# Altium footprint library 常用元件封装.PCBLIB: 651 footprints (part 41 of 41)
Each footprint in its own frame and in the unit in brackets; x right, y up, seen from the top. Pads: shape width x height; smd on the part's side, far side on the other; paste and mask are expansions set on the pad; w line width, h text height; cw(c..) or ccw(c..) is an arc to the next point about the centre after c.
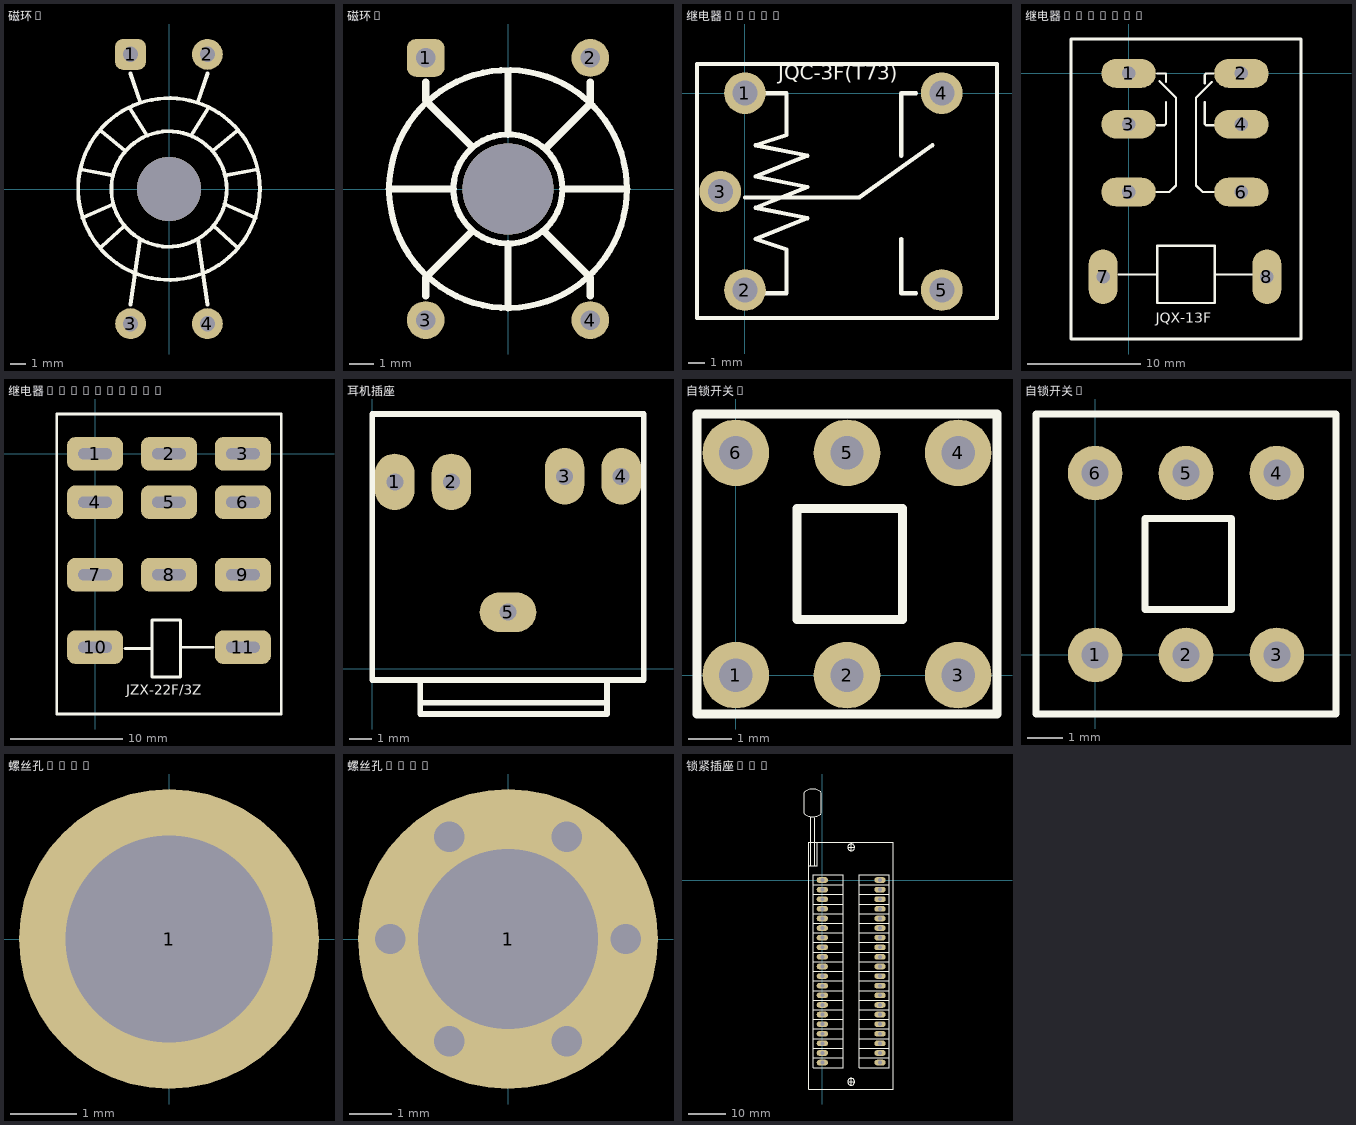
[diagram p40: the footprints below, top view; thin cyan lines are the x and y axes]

## 磁环1 [mil] "外径12mm脚距17.78mm"
pads (4):
  rrect50% 80x80 hole 40: 1(-100,350)
  round 80 hole 40: 2(100,350) 3(-100,-350) 4(100,-350)
via 0,0 diameter 165.35 hole 165.35
TopOverlay:
  circle w10: c0,0 r236.22
  circle w10: c0,0 r150
  lines w10: -225,-75 -145,-40 ; -225,50 -145,35 ; -175,-150 -117.72,-97.49 ; -175,150 -115,100 ; -102.75,211.4 -58.65,140.84 ; -100,-300 -75.7,-129.9 ; -100,300 -75,225 ; 57.25,138.6 102.75,211.4 ; 75,225 100,300 ; 75.7,-129.9 100,-300 ; 115,-95 175,-150 ; 115,100 175,150 ; 145,-40 225,-75 ; 145,35 225,50

## 磁环2 [mil] "外径11mm脚距12mm"
pads (4):
  rrect50% 62x62 hole 32: 1(-135,215)
  round 62 hole 32: 2(135,215) 3(-135,-215) 4(135,-215)
via 0,0 diameter 150 hole 150
TopOverlay:
  circle w10: c0,0 r89.44
  circle w10: c0,0 r195
  lines w12: -195,0 -90,0 ; -135,-175 -135,-155 -135,-145 -60,-70 ; -135,145 -135,175 ; -130,140 -60,70 ; 0,-195 0,-90 ; 0,90 0,190 ; 60,-70 135,-145 135,-175 ; 65,70 135,140 135,175 ; 89.44,0 195,0

## 继电器(T73) [mm] "长19mm宽15mm"
height 15
pads (5):
  round 2.54 hole 1.524: 1(0,0) 2(0,-12) 3(-1.5,-6) 4(12,0) 5(12,-12)
TopOverlay:
  lines w0.254: 0,-6.35 6.985,-6.35 11.43,-3.175 ; 1.27,-12.2 2.54,-12.2 2.54,-9.525 0.635,-8.89 3.81,-7.62 0.635,-6.985 3.81,-5.715 0.635,-5.08 3.81,-3.81 0.635,-3.175 2.54,-2.54 2.54,0 1.27,0 ; 9.525,-8.89 9.525,-12.2 10.43,-12.2 ; 9.525,-3.81 9.525,0 10.43,0 ; -2.921,-13.716 15.367,-13.716 15.367,1.778 -2.921,1.778 -2.921,-13.716
  text "JQC-3F(T73)" at 2.032,0.508 h1.52

## 继电器JQX-13F [mil] "长21mm宽11mm"
pads (8):
  oval 190x100 hole 47.24: 1(0,0) 2(393,0) 3(0,-177) 4(393,-177) 5(0,-413) 6(393,-413)
  oval 100x190 hole 47.24: 7(-89,-708) 8(482,-708)
TopOverlay:
  lines w7.87: -35,-700 100,-700 ; 0,-413 142,-413 165,-390 165,-85 107.5,-27.5 ; 100,-180 125,-180 130,-175 130,-100 ; 100,0 130,0 130,-30 ; 265,-100 265,-175 270,-180 300,-180 ; 265,-35 265,-5 270,0 295,0 ; 290,-30 235,-85 235,-390 258,-413 393,-413 ; 300,-700 435,-700 ; 100,-800 300,-800 300,-600 100,-600 100,-800
  lines w10: -200,-925 600,-925 600,120 -200,120 -200,-925
  text "JQX-13F" at 95,-880 h60

## 继电器JZX-22F/3Z [mm] "JZX-22F/3Z"
pads (11):
  rrect50% 5x3 hole 1 slot 3 at 0 deg: 1(0,0) 2(6.604,0) 3(13.208,0) 4(0,-4.318) 5(6.604,-4.318) 6(13.208,-4.318) 7(0,-10.795) 8(6.604,-10.795) 9(13.208,-10.795) 10(0,-17.272) 11(13.208,-17.272)
TopOverlay:
  lines w0.254: 2.667,-17.399 5.08,-17.399 ; 7.62,-17.272 10.541,-17.272 ; -3.429,-23.241 -3.429,3.556 16.637,3.556 16.637,-23.241 -3.429,-23.241 ; 5.08,-19.939 7.62,-19.939 7.62,-14.859 5.08,-14.859 5.08,-19.939
  text "JZX-22F/3Z" at 2.794,-21.844 h1.52

## 耳机插座 [mil]
pads (5):
  oval 70x100 hole 30: 1(40,330) 2(140,330) 3(340,340) 4(440,340)
  oval 100x70 hole 30: 5(240,100)
TopOverlay:
  lines w10: 0,210 0,230 ; 85,-20 85,-60 ; 230,-20 250,-20 ; 415,-20 415,-60 ; 85,-60 415,-60 ; 85,-60 85,-80 380,-80 415,-80 415,-60 ; 0,-20 0,450 480,450 480,-20 0,-20

## 自锁开关6 [mil] "自锁开关6.6X6.6"
height 492.13
pads (6):
  round 60 hole 30: 1(0,0) 2(100,0) 3(200,0) 4(200,200) 5(100,200) 6(0,200)
TopOverlay:
  lines w8: -35,-35 235,-35 235,235 -35,235 -35,-35 ; 55,50 150,50 150,150 55,150 55,50

## 自锁开关8 [mil] "自锁开关8X8"
height 492.13
pads (6):
  round 60 hole 30: 1(0,0) 2(100,0) 3(200,0) 4(200,200) 5(100,200) 6(0,200)
TopOverlay:
  lines w8: -65,-65 265,-65 265,265 -65,265 -65,-65 ; 55,50 150,50 150,150 55,150 55,50

## 螺丝孔-3mm [mm]
pads (1):
  round 4.5 hole 3.1: 1(0,0)

## 螺丝孔-4mm [mm]
pads (1):
  round 7 hole 4.2: 1(0,0)
via -2.75,0 diameter 1.27 hole 0.711
via 2.75,0 diameter 1.27 hole 0.711
via -1.375,-2.382 diameter 1.27 hole 0.711
via 1.375,2.382 diameter 1.27 hole 0.711
via 1.375,-2.382 diameter 1.27 hole 0.711
via -1.375,2.382 diameter 1.27 hole 0.711

## 锁紧插座-40 [mm]
height 10
pads (40):
  oval 3x1.5 hole 1.016: 1(0,0) 2(0,-2.54) 3(0,-5.08) 4(0,-7.62) 5(0,-10.16) 6(0,-12.7) 7(0,-15.24) 8(0,-17.78) 9(0,-20.32) 10(0,-22.86) 11(0,-25.4) 12(0,-27.94) 13(0,-30.48) 14(0,-33.02) 15(0,-35.56) 16(0,-38.1) 17(0,-40.64) 18(0,-43.18) 19(0,-45.72) 20(0,-48.26) 21(15.24,-48.26) 22(15.24,-45.72) 23(15.24,-43.18) 24(15.24,-40.64) 25(15.24,-38.1) 26(15.24,-35.56) 27(15.24,-33.02) 28(15.24,-30.48) 29(15.24,-27.94) 30(15.24,-25.4) 31(15.24,-22.86) 32(15.24,-20.32) 33(15.24,-17.78) 34(15.24,-15.24) 35(15.24,-12.7) 36(15.24,-10.16) 37(15.24,-7.62) 38(15.24,-5.08) 39(15.24,-2.54) 40(15.24,0)
TopOverlay:
  circle w0.254: c7.62,-53.34 r0.925
  circle w0.254: c7.62,8.636 r0.916
  lines w0.254: -3.556,3.81 -1.397,3.81 -1.397,10.033 ; -3.048,3.81 -3.048,16.637 ; -2.413,-46.99 5.461,-46.99 ; -2.413,-44.45 5.461,-44.45 ; -2.413,-41.91 5.461,-41.91 ; -2.413,-39.37 5.461,-39.37 ; -2.413,-36.83 5.461,-36.83 ; -2.413,-34.29 5.461,-34.29 ; -2.413,-31.75 5.334,-31.75 ; -2.413,-29.21 5.461,-29.21 ; -2.413,-26.67 5.461,-26.67 ; -2.413,-24.13 5.461,-24.13 ; -2.413,-21.59 5.334,-21.59 ; -2.413,-19.05 5.461,-19.05 ; -2.413,-16.51 5.461,-16.51 ; -2.413,-13.97 5.461,-13.97 ; -2.413,-11.43 5.461,-11.43 ; -2.413,-8.89 5.461,-8.89 ; -2.413,-6.35 5.461,-6.35 ; -2.413,-3.81 5.461,-3.81 ; -2.413,-1.27 5.461,-1.27 ; -2.032,3.81 -2.032,16.51 ; 6.731,-53.34 8.545,-53.34 ; 6.731,8.636 8.536,8.636 ; 7.62,-54.229 7.62,-52.451 ; 7.62,7.747 7.62,9.525 ; 9.779,-46.99 17.653,-46.99 ; 9.779,-44.45 17.653,-44.45 ; 9.779,-41.91 17.653,-41.91 ; 9.779,-36.83 17.653,-36.83 ; 9.779,-34.29 17.653,-34.29 ; 9.779,-31.75 17.653,-31.75 ; 9.779,-29.21 17.653,-29.21 ; 9.779,-26.67 17.653,-26.67 ; 9.779,-24.13 17.653,-24.13 ; 9.779,-21.59 17.653,-21.59 ; 9.779,-16.51 17.653,-16.51 ; 9.779,-11.43 17.653,-11.43 ; 9.779,-8.89 17.653,-8.89 ; 9.779,-6.35 17.653,-6.35 ; 9.779,-3.81 17.653,-3.81 ; 9.779,-1.27 17.653,-1.27 ; 9.906,-39.37 17.653,-39.37 ; 9.906,-19.05 17.653,-19.05 ; 9.906,-13.97 17.653,-13.97 ; -4.826,17.653 ccw(c-2.54,19.939) -0.254,17.653 -0.254,23.114 ccw(c-2.54,20.828) -4.826,23.114 -4.826,17.653 ; -3.556,-55.245 18.796,-55.245 18.796,10.033 -3.556,10.033 -3.556,-55.245 ; -2.413,-49.657 5.461,-49.657 5.461,1.397 -2.413,1.397 -2.413,-49.657 ; 9.779,-49.657 17.653,-49.657 17.653,1.397 9.779,1.397 9.779,-49.657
